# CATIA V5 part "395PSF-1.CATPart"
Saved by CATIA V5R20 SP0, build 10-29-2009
Part number: 395PSF-1
Source: Unknown
Property "ARTICLENO": "395PSF-1"
Property "BOMINFO": "395PSF-1"
Property "CODE": "395PSF-1"
Property "D": "29.000"
Property "D1": "38.000"
Property "H": "4.000"
Property "L": "178.500"
Property "L1": "6.000"
Property "L2": "150.000"
Property "L3": "9.000"
Property "L4": "6.000"
Property "LINA": "395PSF-1"
Property "MAXLOAD": "2000 Kg"
Property "MDW": "4000 Kg"
Property "NB": "395PSF-1"
Property "NBSYN": "$CODE."
Property "NN": "395PSF"
Property "NT": "FIAT Lifting Pins"
Property "SUPPLIER": "CF"
Bounding box of the stored display mesh (mm): x 0 to 178.5, y -19 to 19, z -19 to 19
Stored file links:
  C:\Users\Utente\Desktop\3D files 395PSF\395PSF-1.CATPart
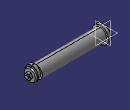
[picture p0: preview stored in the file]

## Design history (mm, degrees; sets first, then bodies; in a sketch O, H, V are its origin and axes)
Body1 "Geometry.1" (main body)
  Solid1 "395PSF-1.catpart": solid without history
